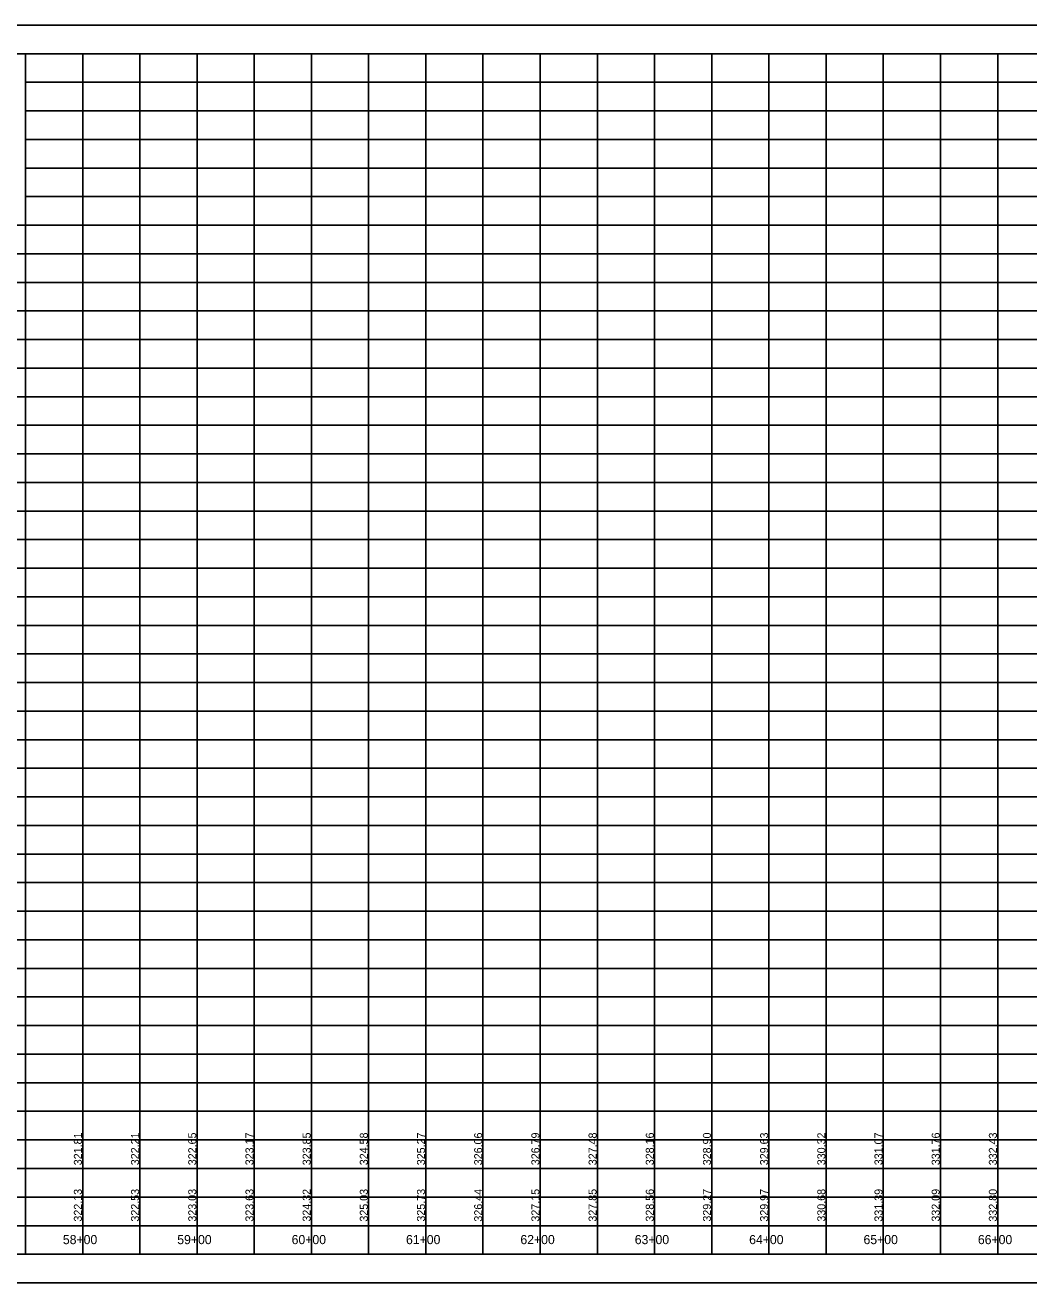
# Model space of a CAD drawing. Extents: x 1873632 to 1926512, y 813126 to 836257.
# Drawn here: x 1884113 to 1884990, y 831005 to 832105 of the extents above; entities that cross this region are included whole.
import ezdxf

# ---------------------------------------------------------------- set-up
doc = ezdxf.new("R2010")
doc.units = 0
for name, color, linetype in [('RD_DDB_StaTX', 7, 'Continuous'), ('RD_DDB_StripGrade', 7, 'Continuous'), ('RD_PD_WallFill', 7, 'Continuous'), ('RD_SHT_IplotShp', 7, 'Continuous')]:
    doc.layers.add(name, color=color, linetype=linetype)

msp = doc.modelspace()

# ---------------------------------------------------------------- linework, layer by layer
at = {"layer": 'RD_PD_WallFill'}
for p, q in [((1883662.8, 832079.6), (1889012.8, 832079.6)), ((1883662.8, 832079.6), (1885412.8, 832079.6)), ((1884112.8, 831029.6), (1884112.8, 832079.6)), ((1884112.8, 831029.6), (1884112.8, 832079.6)), ((1884162.8, 831029.6), (1884162.8, 832079.6)), ((1884162.8, 831029.6), (1884162.8, 832079.6)), ((1884212.8, 831029.6), (1884212.8, 832079.6)), ((1884212.8, 831029.6), (1884212.8, 832079.6)), ((1884262.8, 831029.6), (1884262.8, 832079.6)), ((1884262.8, 831029.6), (1884262.8, 832079.6)), ((1884312.8, 831029.6), (1884312.8, 832079.6)), ((1884312.8, 831029.6), (1884312.8, 832079.6)), ((1884362.8, 831029.6), (1884362.8, 832079.6)), ((1884362.8, 831029.6), (1884362.8, 832079.6)), ((1884412.8, 831029.6), (1884412.8, 832079.6)), ((1884412.8, 831029.6), (1884412.8, 832079.6)), ((1884462.8, 831029.6), (1884462.8, 832079.6)), ((1884462.8, 831029.6), (1884462.8, 832079.6)), ((1884512.8, 831029.6), (1884512.8, 832079.6)), ((1884512.8, 831029.6), (1884512.8, 832079.6)), ((1884562.8, 831029.6), (1884562.8, 832079.6)), ((1884562.8, 831029.6), (1884562.8, 832079.6)), ((1884612.8, 831029.6), (1884612.8, 832079.6)), ((1884612.8, 831029.6), (1884612.8, 832079.6)), ((1884662.8, 831029.6), (1884662.8, 832079.6)), ((1884662.8, 831029.6), (1884662.8, 832079.6)), ((1884712.8, 831029.5), (1884712.8, 832079.6)), ((1884712.8, 831029.5), (1884712.8, 832079.6)), ((1884762.8, 831029.6), (1884762.8, 832079.6)), ((1884762.8, 831029.6), (1884762.8, 832079.6)), ((1884812.8, 831029.6), (1884812.8, 832079.6)), ((1884812.8, 831029.6), (1884812.8, 832079.6)), ((1884862.8, 831029.6), (1884862.8, 832079.6)), ((1884862.8, 831029.6), (1884862.8, 832079.6)), ((1884912.8, 831029.6), (1884912.8, 832079.6)), ((1884912.8, 831029.6), (1884912.8, 832079.6)), ((1884962.8, 831029.6), (1884962.8, 832079.6)), ((1884962.8, 831029.6), (1884962.8, 832079.6)), ((1884112.8, 832054.6), (1889012.8, 832054.6)), ((1884112.8, 832054.6), (1889012.8, 832054.6)), ((1884112.8, 832029.6), (1889012.8, 832029.6)), ((1884112.8, 832004.6), (1889012.8, 832004.6)), ((1884112.8, 831979.6), (1889012.8, 831979.6)), ((1884112.8, 831954.6), (1889012.8, 831954.6)), ((1883662.8, 831929.6), (1889012.8, 831929.6)), ((1883662.8, 831904.6), (1889012.8, 831904.5)), ((1883662.8, 831879.6), (1889012.8, 831879.6)), ((1883662.8, 831854.6), (1889012.8, 831854.5)), ((1883662.8, 831829.6), (1889012.8, 831829.6)), ((1883662.8, 831804.5), (1889012.8, 831804.6)), ((1883662.8, 831779.5), (1889012.8, 831779.6)), ((1883662.8, 831754.6), (1889012.8, 831754.5)), ((1883662.8, 831729.5), (1889012.8, 831729.6)), ((1883662.8, 831704.6), (1889012.8, 831704.6)), ((1883662.8, 831679.6), (1889012.8, 831679.5)), ((1883662.8, 831654.6), (1889012.8, 831654.6)), ((1883662.8, 831629.6), (1889012.8, 831629.5)), ((1883662.8, 831604.6), (1889012.8, 831604.6)), ((1883662.8, 831579.6), (1889012.8, 831579.6)), ((1883662.8, 831554.6), (1889012.8, 831554.5)), ((1883662.8, 831529.6), (1889012.8, 831529.6)), ((1883662.8, 831504.5), (1889012.8, 831504.6)), ((1883662.8, 831479.6), (1889012.8, 831479.6)), ((1883662.8, 831454.6), (1889012.8, 831454.6)), ((1883662.8, 831429.5), (1889012.8, 831429.6)), ((1883662.8, 831404.6), (1889012.8, 831404.5)), ((1883662.8, 831379.6), (1889012.8, 831379.6)), ((1883662.8, 831354.6), (1889012.8, 831354.6)), ((1883662.8, 831329.6), (1889012.8, 831329.5)), ((1883662.8, 831304.6), (1889012.8, 831304.6)), ((1883662.8, 831279.6), (1889012.8, 831279.6)), ((1883662.8, 831254.6), (1889012.8, 831254.6)), ((1883662.8, 831229.6), (1889012.8, 831229.6)), ((1883662.8, 831204.5), (1889012.8, 831204.6)), ((1883662.8, 831179.6), (1889012.8, 831179.5)), ((1883662.8, 831154.6), (1889012.8, 831154.6)), ((1883662.8, 831129.6), (1889012.8, 831129.6)), ((1883662.8, 831104.6), (1889012.8, 831104.6)), ((1883662.8, 831079.6), (1889012.8, 831079.6)), ((1883662.8, 831054.5), (1889012.8, 831054.6)), ((1883662.8, 831029.6), (1889012.8, 831029.5)), ((1883662.8, 831029.6), (1889012.8, 831029.5))]:
    msp.add_line(p, q, dxfattribs=at)
msp.add_lwpolyline([(1883712.8, 832079.6), (1884112.8, 832079.6), (1884112.8, 831929.6), (1883712.8, 831929.6)], close=True, dxfattribs=at)
msp.add_lwpolyline([(1883712.8, 832079.6), (1884112.8, 832079.6), (1884112.8, 831929.6), (1883712.8, 831929.6)], close=True, dxfattribs=at)
msp.add_lwpolyline([(1883712.8, 832079.6), (1884112.8, 832079.6), (1884112.8, 831929.6), (1883712.8, 831929.6)], close=True, dxfattribs=at)
msp.add_lwpolyline([(1883712.8, 832079.6), (1884112.8, 832079.6), (1884112.8, 831929.6), (1883712.8, 831929.6)], close=True, dxfattribs=at)
at = {"layer": 'RD_SHT_IplotShp'}
msp.add_lwpolyline([(1883637.8, 831004.6), (1889037.8, 831004.6), (1889037.8, 832104.6), (1883637.8, 832104.6)], close=True, dxfattribs=at)

# ---------------------------------------------------------------- texts
at = {"layer": 'RD_DDB_StaTX'}
for s, p in [('58+00', (1884145.5, 831038.4)), ('59+00', (1884245.5, 831038.4)), ('60+00', (1884345.5, 831038.4)), ('61+00', (1884445.5, 831038.4)), ('62+00', (1884545.5, 831038.4)), ('63+00', (1884645.5, 831038.4)), ('64+00', (1884745.5, 831038.4)), ('65+00', (1884845.5, 831038.4)), ('66+00', (1884945.5, 831038.4))]:
    msp.add_text(s, height=8, dxfattribs=at).set_placement(p)
at = {"layer": 'RD_DDB_StripGrade'}
for s, p in [('321.81', (1884162.1, 831107.4)), ('322.21', (1884212.1, 831107.4)), ('322.65', (1884262.1, 831107.4)), ('323.17', (1884312.1, 831107.4)), ('323.85', (1884362.1, 831107.4)), ('324.58', (1884412.1, 831107.4)), ('325.27', (1884462.1, 831107.4)), ('326.06', (1884512.1, 831107.4)), ('326.79', (1884562.1, 831107.4)), ('327.48', (1884612.1, 831107.4)), ('328.16', (1884662.1, 831107.4)), ('328.90', (1884712.1, 831107.4)), ('329.63', (1884762.1, 831107.4)), ('330.32', (1884812.1, 831107.4)), ('331.07', (1884862.1, 831107.4)), ('331.76', (1884912.1, 831107.4)), ('332.43', (1884962.1, 831107.4)), ('322.13', (1884162.1, 831058.1)), ('322.53', (1884212.1, 831058.1)), ('323.03', (1884262.1, 831058.1)), ('323.63', (1884312.1, 831058.1)), ('324.32', (1884362.1, 831058.1)), ('325.03', (1884412.1, 831058.1)), ('325.73', (1884462.1, 831058.1)), ('326.44', (1884512.1, 831058.1)), ('327.15', (1884562.1, 831058.1)), ('327.85', (1884612.1, 831058.1)), ('328.56', (1884662.1, 831058.1)), ('329.27', (1884712.1, 831058.1)), ('329.97', (1884762.1, 831058.1)), ('330.68', (1884812.1, 831058.1)), ('331.39', (1884862.1, 831058.1)), ('332.09', (1884912.1, 831058.1)), ('332.80', (1884962.1, 831058.1))]:
    msp.add_text(s, height=7, rotation=90, dxfattribs=at).set_placement(p)

doc.saveas('drawing.dxf')
